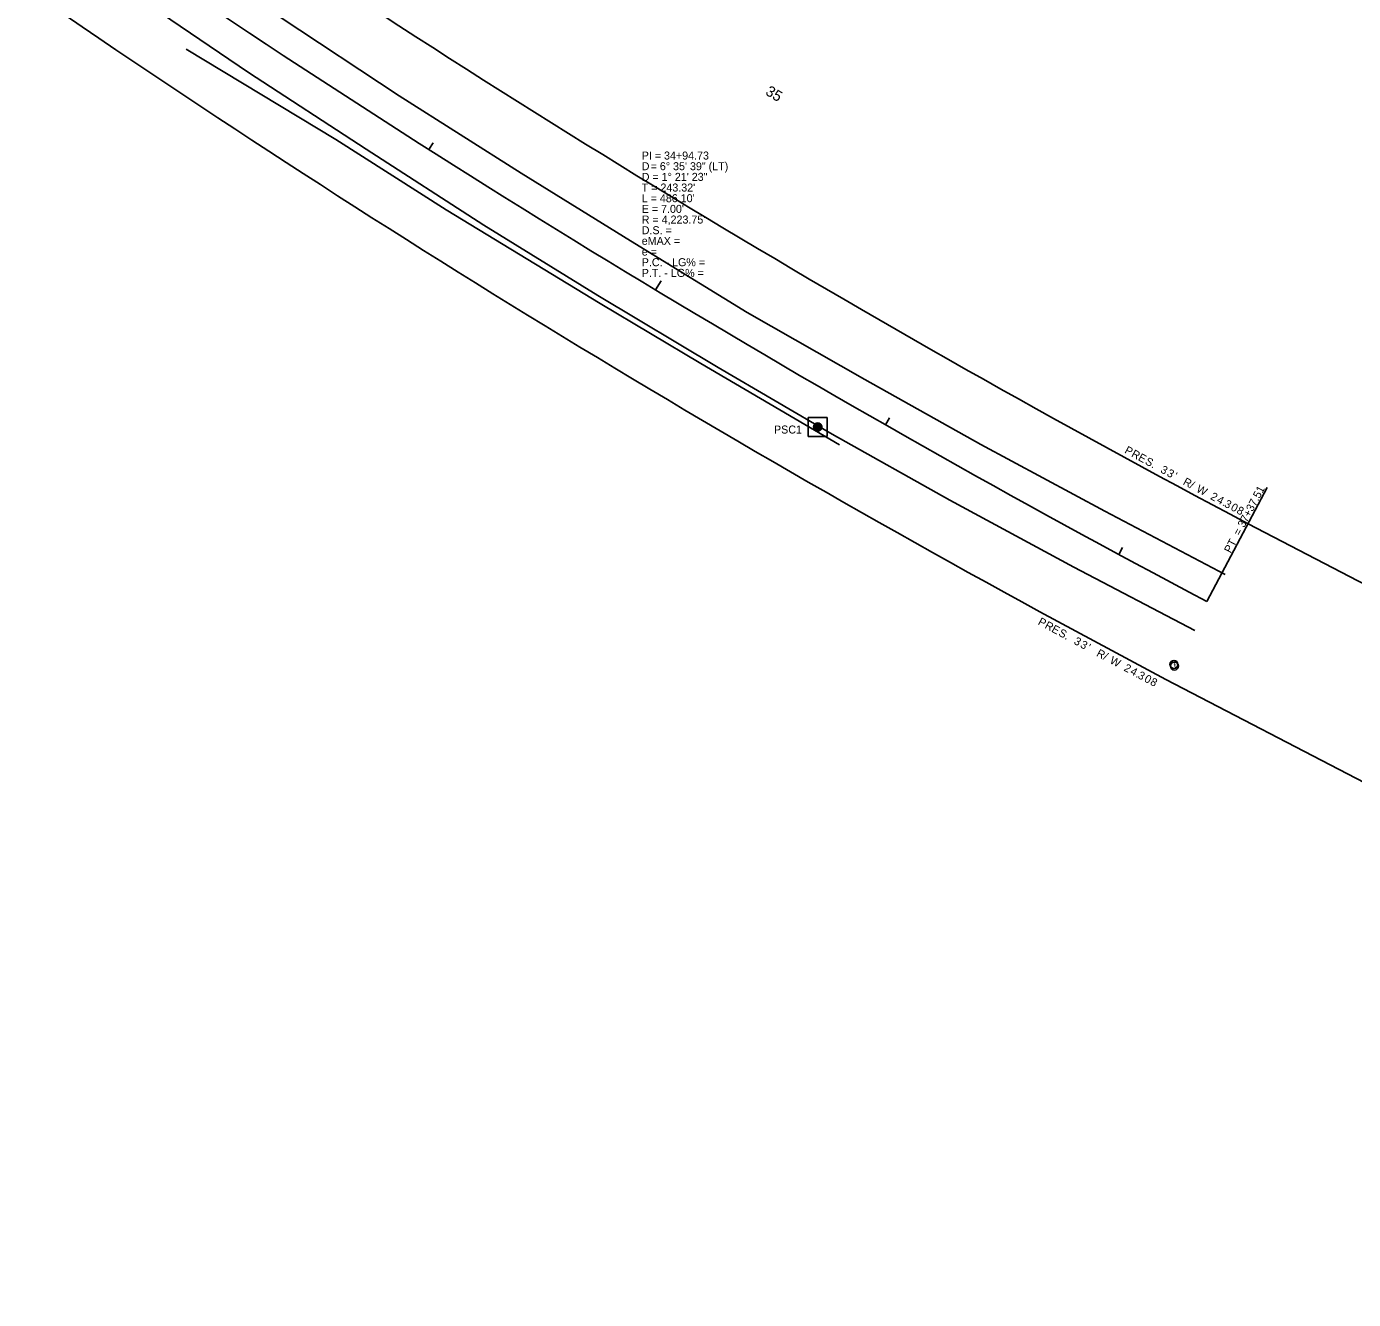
# Model space of a CAD drawing. Extents: x 1687085 to 1692731, y 826429 to 830660.
# Drawn here: x 1690710.3 to 1691207.9, y 828783.6 to 829260.9 of the extents above; entities that cross this region are included whole.
import ezdxf

# ---------------------------------------------------------------- set-up
doc = ezdxf.new("R2010")
doc.units = 0
for name, color, linetype in [('RD_EX_Bridge', 7, 'Continuous'), ('RD_EX_DV_Prop', 7, 'Continuous'), ('RD_EX_Road', 7, 'Continuous'), ('RD_EX_RW', 7, 'Continuous'), ('RD_EX_RW_TX', 7, 'Continuous'), ('RD_EX_SU_Telecom', 7, 'Continuous'), ('RD_EX_UT', 7, 'Continuous'), ('RD_HC_Cl', 7, 'Continuous'), ('RD_HC_Data', 7, 'Continuous'), ('RD_HC_Data_Tic', 7, 'Continuous'), ('RD_HC_Survey', 7, 'Continuous'), ('RD_HC_Survey_txCode', 7, 'Continuous'), ('RD_HC_TX_Sta20', 7, 'Continuous')]:
    doc.layers.add(name, color=color, linetype=linetype)

msp = doc.modelspace()

# ---------------------------------------------------------------- linework, layer by layer
at = {"layer": 'RD_EX_Bridge'}
msp.add_arc((1693126.69, 832779.49), 4223.75, 235.54678, 242.14084, dxfattribs=at)
at = {"layer": 'RD_EX_DV_Prop'}
msp.add_line((1691615.57, 828842.26), (1691168.35, 829074.45), dxfattribs=at)
msp.add_lwpolyline([(1691585.3, 828783.61), (1691585.23, 828783.65), (1691137.51, 829016.1)], dxfattribs=at)
at = {"layer": 'RD_EX_Road'}
for points in [[(1691159.74, 829055.39), (1691114.69, 829079.17), (1691068.19, 829104.14), (1691024.6, 829128.48), (1690980.49, 829153.59), (1690936.85, 829180.48), (1690895.84, 829205.85), (1690850.04, 829234.88), (1690805.39, 829264.43), (1690760.12, 829295.25), (1690716.78, 829324.17), (1690673.22, 829355.13), (1690632.16, 829383.68), (1690592.78, 829410.17), (1690587.41, 829415.33), (1690552.93, 829438.81), (1690511.51, 829466.17), (1690467.43, 829496.42), (1690426.27, 829525.1), (1690383.68, 829554.25)], [(1691148.41, 829034.47), (1691102.99, 829058.12), (1691056.53, 829083.25), (1691012.35, 829108.03), (1690969.64, 829133.05), (1690924.56, 829160.07), (1690881.81, 829186.4), (1690837.69, 829214.92), (1690793.56, 829243.65), (1690746.18, 829275.86), (1690704.43, 829303.98), (1690659.8, 829335.6), (1690619.62, 829363.97), (1690581.14, 829392.07), (1690573.96, 829395.49), (1690539.33, 829419.15), (1690498.2, 829447.81), (1690456.6, 829475.49), (1690413.37, 829505.39), (1690370.29, 829534.15)]]:
    msp.add_lwpolyline(points, dxfattribs=at)
at = {"layer": 'RD_EX_RW'}
for radius, start in [(4190.75, 235.54724), (4256.75, 235.54678)]:
    msp.add_arc((1693126.69, 832779.49), radius, start, 242.14084, dxfattribs=at)
at = {"layer": 'RD_EX_SU_Telecom'}
msp.add_lwpolyline([(1690770.15, 829252.35), (1690826.32, 829218.54), (1690867.72, 829192.2), (1690925.47, 829157.03), (1690963.15, 829134.55), (1691015.19, 829104.04)], dxfattribs=at)
at = {"layer": 'RD_EX_UT'}
for centre in [(1691140.56, 829021.7), (1691140.77, 829021.1)]:
    msp.add_circle(centre, 1.5, dxfattribs=at)
at = {"layer": 'RD_HC_Cl'}
msp.add_arc((1693126.69, 832779.49), 4223.75, 235.54678, 242.14084, dxfattribs=at)
at = {"layer": 'RD_HC_Data'}
msp.add_line((1691152.93, 829045.28), (1691175.53, 829088.02), dxfattribs=at)
at = {"layer": 'RD_HC_Data_Tic'}
for p, q in [((1690861.15, 829214.74), (1690862.76, 829217.28)), ((1690946.18, 829162.11), (1690948.24, 829165.54)), ((1691032.43, 829111.5), (1691033.91, 829114.11)), ((1691119.85, 829062.95), (1691121.27, 829065.59))]:
    msp.add_line(p, q, dxfattribs=at)
at = {"layer": 'RD_HC_Survey'}
for p, q in [((1691005.48, 829110.34), (1691005.48, 829111.06)), ((1691005.53, 829110.17), (1691005.53, 829111.23)), ((1691005.58, 829110.05), (1691005.58, 829111.35)), ((1691005.63, 829109.95), (1691005.63, 829111.45)), ((1691005.68, 829109.87), (1691005.68, 829111.54)), ((1691005.73, 829109.79), (1691005.73, 829111.61)), ((1691005.78, 829109.73), (1691005.78, 829111.68)), ((1691005.83, 829109.67), (1691005.83, 829111.73)), ((1691005.88, 829109.62), (1691005.88, 829111.79)), ((1691005.93, 829109.57), (1691005.93, 829111.84)), ((1691005.98, 829109.52), (1691005.98, 829111.88)), ((1691006.03, 829109.48), (1691006.03, 829111.92)), ((1691006.08, 829109.44), (1691006.08, 829111.96)), ((1691006.13, 829109.41), (1691006.13, 829112)), ((1691006.18, 829109.38), (1691006.18, 829112.03)), ((1691006.23, 829109.35), (1691006.23, 829112.06)), ((1691006.28, 829109.32), (1691006.28, 829112.08)), ((1691006.33, 829109.3), (1691006.33, 829112.11)), ((1691006.38, 829109.27), (1691006.38, 829112.13)), ((1691006.43, 829109.25), (1691006.43, 829112.15)), ((1691006.48, 829109.23), (1691006.48, 829112.17)), ((1691006.53, 829109.22), (1691006.53, 829112.19)), ((1691006.58, 829109.2), (1691006.58, 829112.2)), ((1691006.63, 829109.19), (1691006.63, 829112.21)), ((1691006.68, 829109.18), (1691006.68, 829112.22)), ((1691006.73, 829109.17), (1691006.73, 829112.23)), ((1691006.78, 829109.16), (1691006.78, 829112.24)), ((1691006.83, 829109.16), (1691006.83, 829112.25)), ((1691006.88, 829109.15), (1691006.88, 829112.25)), ((1691006.93, 829109.15), (1691006.93, 829112.26)), ((1691006.98, 829109.15), (1691006.98, 829112.26)), ((1691007.03, 829109.15), (1691007.03, 829112.26)), ((1691007.08, 829109.15), (1691007.08, 829112.25)), ((1691007.13, 829109.15), (1691007.13, 829112.25)), ((1691007.18, 829109.16), (1691007.18, 829112.25)), ((1691007.23, 829109.17), (1691007.23, 829112.24)), ((1691007.28, 829109.17), (1691007.28, 829112.23)), ((1691007.33, 829109.18), (1691007.33, 829112.22)), ((1691007.38, 829109.2), (1691007.38, 829112.21)), ((1691007.43, 829109.21), (1691007.43, 829112.19)), ((1691007.48, 829109.23), (1691007.48, 829112.18)), ((1691007.53, 829109.24), (1691007.53, 829112.16)), ((1691007.58, 829109.26), (1691007.58, 829112.14)), ((1691007.63, 829109.28), (1691007.63, 829112.12)), ((1691007.68, 829109.31), (1691007.68, 829112.1)), ((1691007.73, 829109.33), (1691007.73, 829112.07)), ((1691007.78, 829109.36), (1691007.78, 829112.04)), ((1691007.83, 829109.39), (1691007.83, 829112.01)), ((1691007.88, 829109.43), (1691007.88, 829111.98)), ((1691007.93, 829109.46), (1691007.93, 829111.94)), ((1691007.98, 829109.5), (1691007.98, 829111.9)), ((1691008.03, 829109.54), (1691008.03, 829111.86)), ((1691008.08, 829109.59), (1691008.08, 829111.81)), ((1691008.13, 829109.64), (1691008.13, 829111.76)), ((1691008.18, 829109.7), (1691008.18, 829111.7)), ((1691008.23, 829109.76), (1691008.23, 829111.64)), ((1691008.28, 829109.83), (1691008.28, 829111.57)), ((1691008.33, 829109.91), (1691008.33, 829111.49)), ((1691008.38, 829110), (1691008.38, 829111.4)), ((1691008.43, 829110.11), (1691008.43, 829111.29)), ((1691008.48, 829110.25), (1691008.48, 829111.15)), ((1691008.53, 829110.48), (1691008.53, 829110.93))]:
    msp.add_line(p, q, dxfattribs=at)
msp.add_lwpolyline([(1691010.53, 829114.24), (1691003.45, 829114.24), (1691003.45, 829107.17), (1691010.53, 829107.17)], close=True, dxfattribs=at)
msp.add_circle((1691006.99, 829110.7), 1.55, dxfattribs=at)

# ---------------------------------------------------------------- texts
at = {"layer": 'RD_EX_RW_TX'}
for s, rotation, p in [('P', 331.4272, (1691121.81, 829101.13)), ('R', 331.4667, (1691124.35, 829099.76)), ('E', 331.5061, (1691126.88, 829098.38)), ('S', 331.5468, (1691129.49, 829096.96)), ('.', 331.5843, (1691131.9, 829095.65)), ('3', 331.6363, (1691135.25, 829093.85)), ('3', 331.6737, (1691137.66, 829092.54)), ("'", 331.7112, (1691140.07, 829091.24)), ('R', 331.7678, (1691143.71, 829089.28)), ('/', 331.8072, (1691146.25, 829087.92)), ('W', 331.8453, (1691148.71, 829086.6)), ('2', 331.927, (1691153.98, 829083.79)), ('4', 331.9639, (1691156.35, 829082.52)), ('.', 331.9968, (1691158.48, 829081.39)), ('3', 332.0078, (1691159.19, 829081.01)), ('0', 332.0453, (1691161.61, 829079.72)), ('8', 332.0795, (1691163.82, 829078.55)), ('P', 331.4572, (1691089.33, 829036.84)), ('R', 331.4959, (1691091.87, 829035.46)), ('E', 331.5347, (1691094.4, 829034.08)), ('S', 331.5748, (1691097.02, 829032.66)), ('.', 331.6116, (1691099.43, 829031.36)), ('3', 331.6628, (1691102.78, 829029.55)), ('3', 331.6997, (1691105.19, 829028.25)), ("'", 331.7366, (1691107.61, 829026.95)), ('R', 331.7922, (1691111.25, 829024.99)), ('/', 331.831, (1691113.79, 829023.63)), ('W', 331.8685, (1691116.25, 829022.31)), ('2', 331.9489, (1691121.53, 829019.49)), ('4', 331.9851, (1691123.91, 829018.23)), ('.', 332.0175, (1691126.03, 829017.09)), ('3', 332.0283, (1691126.74, 829016.72)), ('0', 332.0652, (1691129.17, 829015.43)), ('8', 332.0989, (1691131.38, 829014.26))]:
    msp.add_text(s, height=3, rotation=rotation, dxfattribs=at).set_placement(p)
at = {"layer": 'RD_EX_UT'}
for p in [(1691140.21, 829020.88), (1691140.42, 829020.29)]:
    msp.add_text('T', height=1.5, rotation=360, dxfattribs=at).set_placement(p)
at = {"layer": 'RD_HC_Data'}
for s, p in [('PI = 34+94.73', (1690941, 829211)), ('D', (1690941, 829207)), ('   = 6%%d 35\' 39" (LT)', (1690941, 829207)), ('D = 1%%d 21\' 23"', (1690941, 829203)), ("T = 243.32'", (1690941, 829199)), ("L = 486.10'", (1690941, 829195)), ("E = 7.00'", (1690941, 829191)), ("R = 4,223.75'", (1690941, 829187)), ('D.S. = ', (1690941, 829183)), ('eMAX = ', (1690941, 829179)), ('e = ', (1690941, 829175)), ('P.C. - LG% = ', (1690941, 829171)), ('P.T. - LG% = ', (1690941, 829167))]:
    msp.add_text(s, height=3, dxfattribs=at).set_placement(p)
msp.add_text('PT  = 37+37.51', height=3, rotation=62.1408, dxfattribs=at).set_placement((1691161.84, 829063.19))
at = {"layer": 'RD_HC_Survey_txCode'}
msp.add_text('PSC1', height=3, dxfattribs=at).set_placement((1690990.6, 829108.27))
at = {"layer": 'RD_HC_TX_Sta20'}
msp.add_text('35', height=4, rotation=328.9189, dxfattribs=at).set_placement((1690987.08, 829235.54))

doc.saveas('drawing.dxf')
